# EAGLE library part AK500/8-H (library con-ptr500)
CONNECTOR Aug. 2004 / PTR Meßtechnik: Die Bezeichnung der Serie AK505 wurde geändert. Es handelt sich hierbei um AK500 in horizontaler Ausführung.
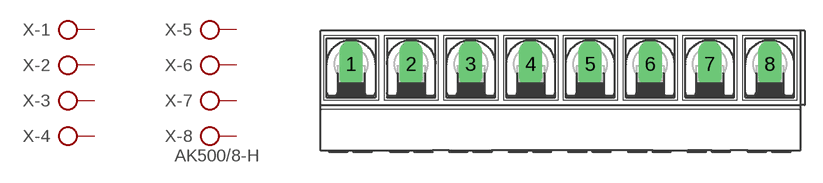
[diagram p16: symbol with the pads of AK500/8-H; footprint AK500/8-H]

Designator prefix X; gates -1=KL -2=KL -3=KL -4=KL -5=KL -6=KL -7=KL -8=KLV

## AK500/8-H (OC_FARNELL: unknown; OC_NEWARK: unknown)  [AK500/8-H]
1  -1:KL  pas
2  -2:KL  pas
3  -3:KL  pas
4  -4:KL  pas
5  -5:KL  pas
6  -6:KL  pas
7  -7:KL  pas
8  -8:KL  pas

## Footprint AK500/8-H (pad centres in mm)
CONNECTOR Aug. 2004 / PTR Meßtechnik: Die Bezeichnung der Serie AK505 wurde geändert. Es handelt sich hierbei um AK500 in horizontaler Ausführung.
drill 1.321 long: 1 -17.526,0; 2 -12.497,0; 3 -7.518,0; 4 -2.489,0; 5 2.489,0; 6 7.518,0; 7 12.497,0; 8 17.526,0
